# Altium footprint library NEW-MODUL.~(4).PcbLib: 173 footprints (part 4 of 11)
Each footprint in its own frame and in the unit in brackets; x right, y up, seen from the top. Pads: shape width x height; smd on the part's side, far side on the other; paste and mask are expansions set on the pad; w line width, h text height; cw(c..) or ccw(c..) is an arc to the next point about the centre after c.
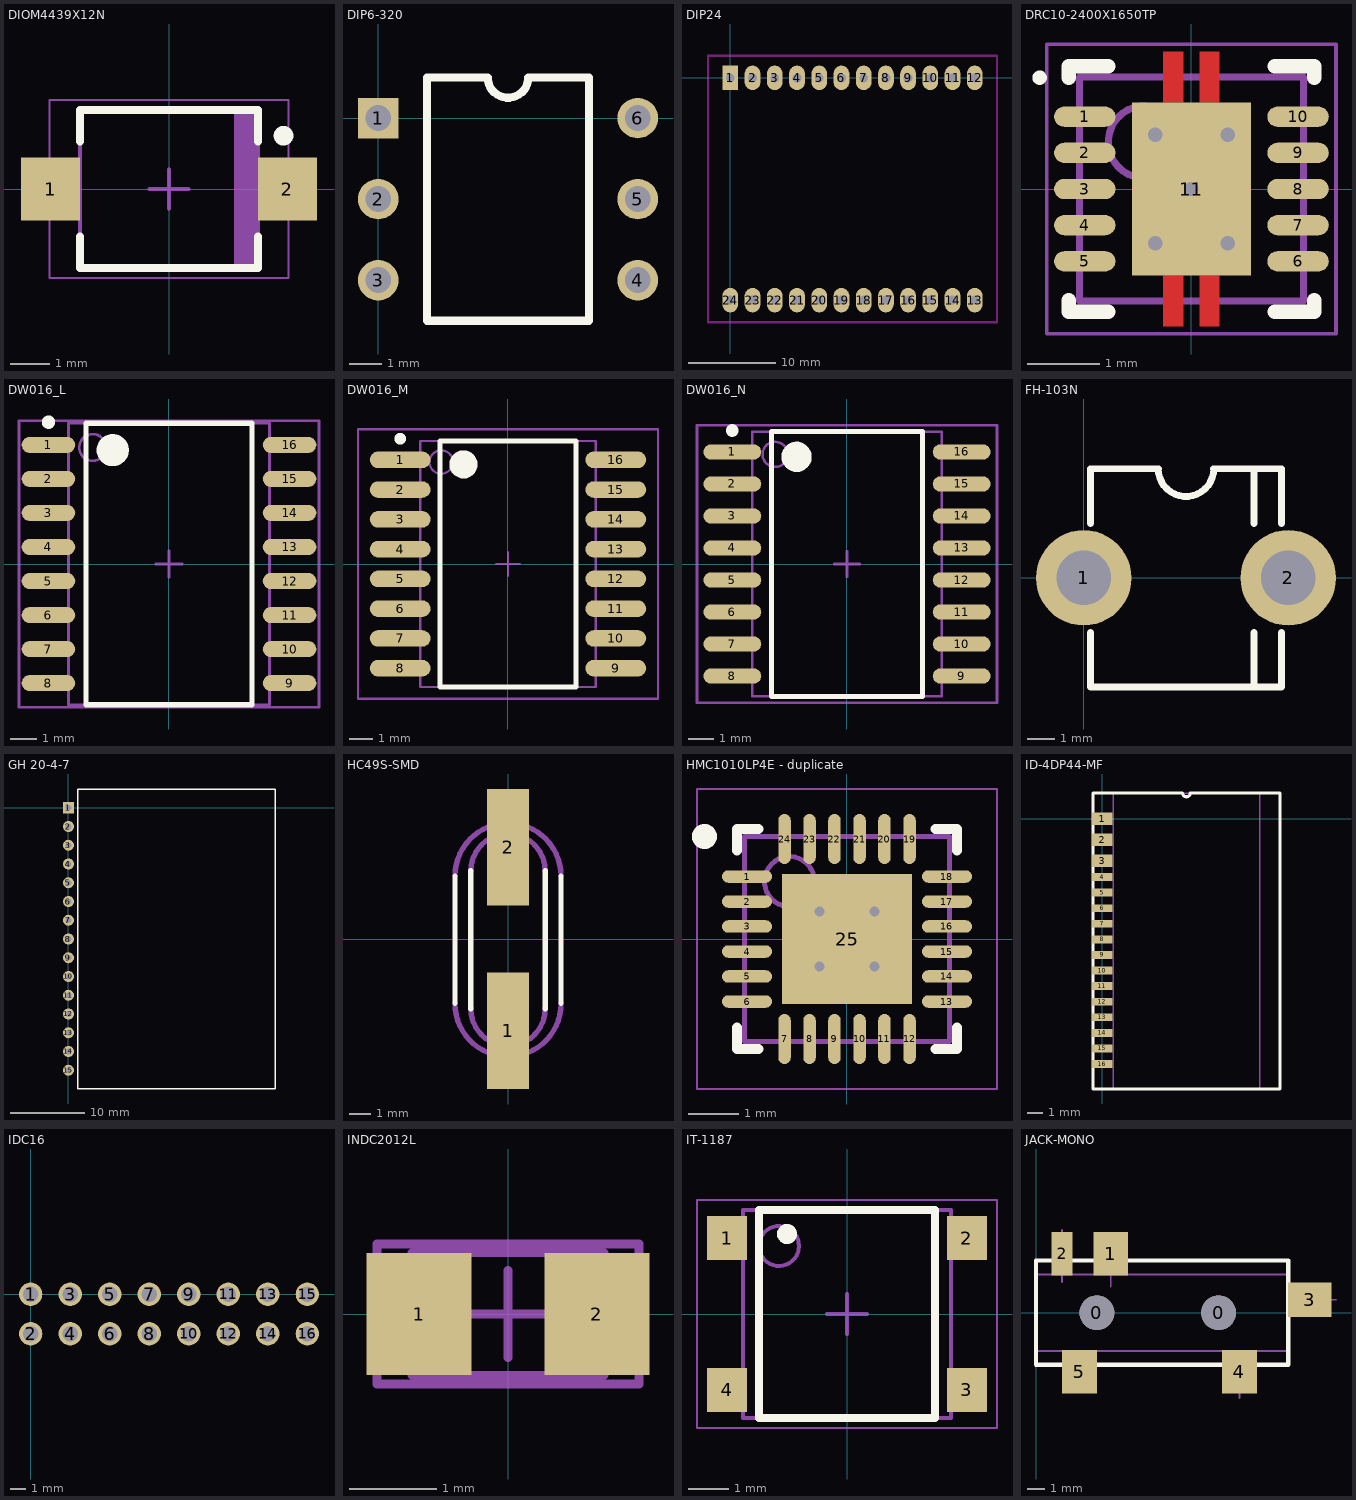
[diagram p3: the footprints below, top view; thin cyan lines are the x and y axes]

## DIOM4439X12N [mm] "Molded Diode, 2-Leads, Body 4,40x3,85mm, IPC Medium Density"
height 1.2
pads (2):
  rect 1.5x1.6 smd: 1(-3,0) 2(3,0)
Top Overlay:
  circle w0.25: c2.9,1.35 r0.125
  lines w0.2: -2.25,-1.2 -2.25,-2 2.25,-2 2.25,-1.2 ; -2.25,1.2 -2.25,2 2.25,2 2.25,1.2
Mechanical 13:
  rectangle: 1.645,-2 2.25,2
  lines w0.1: -2.25,-2 2.25,-2 2.25,2 -2.25,2 -2.25,-2
Mechanical 15:
  lines w0.05: -3.025,-2.25 3.025,-2.25 3.025,2.25 -3.025,2.25 -3.025,-2.25
  lines w0.1: -0.5,0 0.5,0 ; 0,-0.5 0,0.5
3D body: height 1.2, standoff 0, extent -2.25,-2 2.25,2

## DIP6-320 [mil]
pads (6):
  rect 50x50 hole 32: 1(0,0)
  round 50 hole 32: 2(0,-100) 3(0,-200) 4(320,-200) 5(320,-100) 6(320,0)
Top Overlay:
  lines w10: 60,-250 260,-250 260,50 185,50 cw(c160,50) 135,50 60,50 60,-250
3D body "4N33_DIL06.stp": height 177.17, standoff -115.06, extent -13.76,-267.71 328.71,70.87

## DIP24 [mm]
pads (24):
  rect 1.8x2.8 hole 1: 1(0,0)
  oval 1.8x2.8 hole 1: 2(2.54,0) 3(5.08,0) 4(7.62,0) 5(10.16,0) 6(12.7,0) 7(15.24,0) 8(17.78,0) 9(20.32,0) 10(22.86,0) 11(25.4,0) 12(27.94,0) 13(27.94,-25.4) 14(25.4,-25.4) 15(22.86,-25.4) 16(20.32,-25.4) 17(17.78,-25.4) 18(15.24,-25.4) 19(12.7,-25.4) 20(10.16,-25.4) 21(7.62,-25.4) 22(5.08,-25.4) 23(2.54,-25.4) 24(0,-25.4)
Bottom Overlay:
  lines w0.254: -2.54,-13.97 ccw(c-2.54,-12.7) -2.54,-11.43
Keep-Out Layer:
  lines w0.254: -2.54,-27.94 30.48,-27.94 30.48,2.54 -2.54,2.54 -2.54,-27.94
3D body "User Library-PLS-1.step": height 8.44, standoff -3, extent 26.67,-26.67 29.21,-24.13
3D body "User Library-PLS-1.step": height 8.44, standoff -3, extent 24.13,-26.67 26.67,-24.13
3D body "User Library-PLS-1.step": height 8.44, standoff -3, extent 21.59,-26.67 24.13,-24.13
3D body "User Library-PLS-1.step": height 8.44, standoff -3, extent 19.05,-26.67 21.59,-24.13
3D body "User Library-PLS-1.step": height 8.44, standoff -3, extent 16.51,-26.67 19.05,-24.13
3D body "User Library-PLS-1.step": height 8.44, standoff -3, extent 13.97,-26.67 16.51,-24.13
3D body "User Library-PLS-1.step": height 8.44, standoff -3, extent 11.43,-26.67 13.97,-24.13
3D body "User Library-PLS-1.step": height 8.44, standoff -3, extent 8.89,-26.67 11.43,-24.13
3D body "User Library-PLS-1.step": height 8.44, standoff -3, extent 6.35,-26.67 8.89,-24.13
3D body "User Library-PLS-1.step": height 8.44, standoff -3, extent 3.81,-26.67 6.35,-24.13
3D body "User Library-PLS-1.step": height 8.44, standoff -3, extent 1.27,-26.67 3.81,-24.13
3D body "User Library-PLS-1.step": height 8.44, standoff -3, extent -1.27,-26.67 1.27,-24.13
3D body "User Library-PLS-1.step": height 8.44, standoff -3, extent 26.67,-1.27 29.21,1.27
3D body "User Library-PLS-1.step": height 8.44, standoff -3, extent 24.13,-1.27 26.67,1.27
3D body "User Library-PLS-1.step": height 8.44, standoff -3, extent 21.59,-1.27 24.13,1.27
3D body "User Library-PLS-1.step": height 8.44, standoff -3, extent 19.05,-1.27 21.59,1.27
3D body "User Library-PLS-1.step": height 8.44, standoff -3, extent 16.51,-1.27 19.05,1.27
3D body "User Library-PLS-1.step": height 8.44, standoff -3, extent 13.97,-1.27 16.51,1.27
3D body "User Library-PLS-1.step": height 8.44, standoff -3, extent 11.43,-1.27 13.97,1.27
3D body "User Library-PLS-1.step": height 8.44, standoff -3, extent 8.89,-1.27 11.43,1.27
3D body "User Library-PLS-1.step": height 8.44, standoff -3, extent 6.35,-1.27 8.89,1.27
3D body "User Library-PLS-1.step": height 8.44, standoff -3, extent 3.81,-1.27 6.35,1.27
3D body "User Library-PLS-1.step": height 8.44, standoff -3, extent 1.27,-1.27 3.81,1.27
3D body "User Library-PLS-1.step": height 8.44, standoff -3, extent -1.27,-1.27 1.27,1.27

## DRC10-2400X1650TP [mm] "SON, 10-Leads, Body 3x3mm, Pitch 0.5mm, Thermal Pad 2.4x1.65mm, TI Recommended"
height 1
pads (11):
  oval 0.85x0.28 smd paste-0.025 mask+0.07: 1(-1.475,1) 2(-1.475,0.5) 3(-1.475,0) 4(-1.475,-0.5) 5(-1.475,-1) 6(1.475,-1) 7(1.475,-0.5) 8(1.475,0) 9(1.475,0.5) 10(1.475,1)
  rect 1.65x2.4 smd paste-0.825 mask+0.07: 11(0,0)
via 0.5,-0.75 diameter 0.5 hole 0.2
via -0.5,-0.75 diameter 0.5 hole 0.2
via -0.5,0.75 diameter 0.5 hole 0.2
via 0.5,0.75 diameter 0.5 hole 0.2
via 0,0 diameter 0.5 hole 0.2
Top Layer:
  rectangle: -0.39,-1.9 -0.11,-1.2
  region: 0.39,-1.2 0.11,-1.2 0.11,-1.9 0.39,-1.9
  region: 0.39,1.9 0.11,1.9 0.11,1.2 0.39,1.2
  rectangle: -0.39,1.2 -0.11,1.9
Top Overlay:
  circle w0.1: c-2.1,1.54 r0.05
  lines w0.2: -1.7,-1.54 -1.7,-1.7 -1.15,-1.7 ; -1.7,1.54 -1.7,1.7 -1.15,1.7 ; 1.15,-1.7 1.7,-1.7 1.7,-1.54 ; 1.15,1.7 1.7,1.7 1.7,1.54
Top Paste:
  rectangle: -0.79,-1.16 -0.11,-0.11
  region: 0.79,-0.11 0.11,-0.11 0.11,-1.16 0.79,-1.16
  region: 0.79,1.16 0.11,1.16 0.11,0.11 0.79,0.11
  rectangle: -0.38,-1.88 -0.12,-1.38
  region: 0.38,-1.38 0.12,-1.38 0.12,-1.88 0.38,-1.88
  region: 0.38,1.88 0.12,1.88 0.12,1.38 0.38,1.38
  rectangle: -0.38,1.38 -0.12,1.88
  rectangle: -0.79,0.11 -0.11,1.16
Mechanical 13:
  circle w0.1: c-0.65,0.65 r0.5
  lines w0.1: -1.55,-1.55 1.55,-1.55 1.55,1.55 -1.55,1.55 -1.55,-1.55
Mechanical 15:
  lines w0.05: -2,-2 2,-2 2,2 -2,2 -2,-2
3D body: height 1, standoff 0, extent -1.55,-1.55 1.55,1.55

## DW016_L [mm] "16-Pin Plastic Small Outline Integrated Circuit 1.27 mm Pitch, IPC High Density"
height 2.65
pads (16):
  oval 2x0.6 smd: 1(-4.5,4.445) 2(-4.5,3.175) 3(-4.5,1.905) 4(-4.5,0.635) 5(-4.5,-0.635) 6(-4.5,-1.905) 7(-4.5,-3.175) 8(-4.5,-4.445) 9(4.5,-4.445) 10(4.5,-3.175) 11(4.5,-1.905) 12(4.5,-0.635) 13(4.5,0.635) 14(4.5,1.905) 15(4.5,3.175) 16(4.5,4.445)
Top Overlay:
  circle w0.25: c-4.5,5.295 r0.125
  circle w0.6: c-2.1,4.25 r0.3
  lines w0.2: -3.1,-5.25 -3.1,5.25 3.1,5.25 3.1,-5.25 -3.1,-5.25
Mechanical 13:
  circle w0.1: c-2.85,4.35 r0.5
  lines w0.1: -3.75,-5.25 -3.75,5.25 3.75,5.25 3.75,-5.25 -3.75,-5.25
Mechanical 15:
  lines w0.1: -0.5,0 0.5,0 ; 0,-0.5 0,0.5 ; -5.6,-5.35 -5.6,5.35 5.6,5.35 5.6,-5.35 -5.6,-5.35
3D body: height 2.65, standoff 0, extent -3.75,-5.25 3.75,5.25

## DW016_M [mm] "16-Pin Plastic Small Outline Integrated Circuit 1.27 mm Pitch, IPC Low Density"
height 2.65
pads (16):
  oval 2.6x0.7 smd: 1(-4.6,4.445) 2(-4.6,3.175) 3(-4.6,1.905) 4(-4.6,0.635) 5(-4.6,-0.635) 6(-4.6,-1.905) 7(-4.6,-3.175) 8(-4.6,-4.445) 9(4.6,-4.445) 10(4.6,-3.175) 11(4.6,-1.905) 12(4.6,-0.635) 13(4.6,0.635) 14(4.6,1.905) 15(4.6,3.175) 16(4.6,4.445)
Top Overlay:
  circle w0.6: c-1.9,4.25 r0.3
  circle w0.25: c-4.6,5.345 r0.125
  lines w0.2: -2.9,-5.25 2.9,-5.25 2.9,5.25 -2.9,5.25 -2.9,-5.25
Mechanical 13:
  circle w0.1: c-2.85,4.35 r0.5
  lines w0.1: -3.75,-5.25 3.75,-5.25 3.75,5.25 -3.75,5.25 -3.75,-5.25
Mechanical 15:
  lines w0.1: -0.5,0 0.5,0 ; 0,-0.5 0,0.5 ; -6.4,-5.75 6.4,-5.75 6.4,5.75 -6.4,5.75 -6.4,-5.75
3D body: height 2.65, standoff 0, extent -3.75,-5.25 3.75,5.25

## DW016_N [mm] "16-Pin Plastic Small Outline Integrated Circuit 1.27 mm Pitch, IPC Medium Density"
height 2.65
pads (16):
  oval 2.3x0.6 smd: 1(-4.55,4.445) 2(-4.55,3.175) 3(-4.55,1.905) 4(-4.55,0.635) 5(-4.55,-0.635) 6(-4.55,-1.905) 7(-4.55,-3.175) 8(-4.55,-4.445) 9(4.55,-4.445) 10(4.55,-3.175) 11(4.55,-1.905) 12(4.55,-0.635) 13(4.55,0.635) 14(4.55,1.905) 15(4.55,3.175) 16(4.55,4.445)
Top Overlay:
  circle w0.25: c-4.55,5.295 r0.125
  circle w0.6: c-2,4.25 r0.3
  lines w0.2: -3,-5.25 -3,5.25 3,5.25 3,-5.25 -3,-5.25
Mechanical 13:
  circle w0.1: c-2.85,4.35 r0.5
  lines w0.1: -3.75,-5.25 -3.75,5.25 3.75,5.25 3.75,-5.25 -3.75,-5.25
Mechanical 15:
  lines w0.1: -0.5,0 0.5,0 ; 0,-0.5 0,0.5 ; -5.95,-5.5 -5.95,5.5 5.95,5.5 5.95,-5.5 -5.95,-5.5
3D body "User Library-SOIC16-300.step": height 2.65, standoff 0, extent -5.15,-5.15 5.15,5.15

## FH-103N [mm]
pads (2):
  round 3.5 hole 2: 1(0,0) 2(7.5,0)
Top Overlay:
  lines w0.254: 0.25,-2 0.25,-4 7.25,-4 7.25,-2 ; 0.25,2 0.25,4 2.734,4 ccw(c3.75,4) 4.766,4 7.25,4 7.25,2 ; 6.25,-4 6.25,-2 6.25,-4 ; 6.25,2 6.25,4 6.25,2
3D body "User Library-LF-102071.step": height 10.89, standoff -3.6, extent -0.24,-3.95 7.86,3.95

## GH 20-4-7 [mm]
height 3
pads (15):
  rect 1.5x1.5 hole 0.8: 1(0,0)
  round 1.5 hole 0.8: 2(0,-2.54) 3(0,-5.08) 4(0,-7.62) 5(0,-10.16) 6(0,-12.7) 7(0,-15.24) 8(0,-17.78) 9(0,-20.32) 10(0,-22.86) 11(0,-25.4) 12(0,-27.94) 13(0,-30.48) 14(0,-33.02) 15(0,-35.56)
Top Overlay:
  lines w0.2: 1.25,-38.1 28,-38.1 28,2.54 1.25,2.54 1.25,-38.1

## HC49S-SMD [mm]
pads (2):
  rect 2x5.5 smd: 1(0,-4.318) 2(0,4.318)
Top Overlay:
  lines w0.25: -2.5,-3.04 -2.5,2.96 ; -1.75,-3.29 -1.75,3.21 ; 1.75,-3.29 1.75,3.21 ; 2.5,-3.04 2.5,2.96
Mechanical 1:
  lines w0.25: -2.5,-3.036 ccw(c0,-3.04) 2.5,-3.036 ; -2.5,2.964 cw(c0,2.96) 2.5,2.964 ; -1.75,-3.287 ccw(c0,-3.29) 1.75,-3.287 ; -1.75,3.213 cw(c0,3.21) 1.75,3.213
3D body "User Library-SMU-4.step": height 4, standoff 0, extent -2.4,-6.25 2.4,6.25

## HMC1010LP4E - duplicate [mm]
pads (25):
  oval 1x0.25 smd: 1(-2,1.25) 2(-2,0.75) 3(-2,0.25) 4(-2,-0.25) 5(-2,-0.75) 6(-2,-1.25) 13(2,-1.25) 14(2,-0.75) 15(2,-0.25) 16(2,0.25) 17(2,0.75) 18(2,1.25)
  oval 0.25x1 smd: 7(-1.25,-2) 8(-0.75,-2) 9(-0.25,-2) 10(0.25,-2) 11(0.75,-2) 12(1.25,-2) 19(1.25,2) 20(0.75,2) 21(0.25,2) 22(-0.25,2) 23(-0.75,2) 24(-1.25,2)
  rect 2.6x2.6 smd: 25(0,0)
via -0.55,0.55 diameter 0.5 hole 0.2
via 0.55,0.55 diameter 0.5 hole 0.2
via -0.55,-0.55 diameter 0.5 hole 0.2
via 0.55,-0.55 diameter 0.5 hole 0.2
Top Overlay:
  circle w0.25: c-2.85,2.05 r0.125
  lines w0.2: -2.2,-1.775 -2.2,-2.2 -1.775,-2.2 ; -2.2,1.775 -2.2,2.2 -1.775,2.2 ; 1.775,-2.2 2.2,-2.2 2.2,-1.775 ; 1.775,2.2 2.2,2.2 2.2,1.775
Mechanical 13:
  circle w0.1: c-1.15,1.15 r0.5
  lines w0.1: -2.05,-2.05 -2.05,2.05 2.05,2.05 2.05,-2.05 -2.05,-2.05
Mechanical 15:
  lines w0.05: -3,-3 -3,3 3,3 3,-3 -3,-3
  lines w0.1: -0.5,0 0.5,0 ; 0,-0.5 0,0.5
3D body: height 1, standoff 0, extent -2.05,-2.05 2.05,2.05

## ID-4DP44-MF [mm]
pads (16):
  rect 1.3x0.8 smd: 1(0,0) 2(0,-1.35) 3(0,-2.7)
  rect 1.3x0.5 smd: 4(0,-3.75) 5(0,-4.75) 6(0,-5.75) 7(0,-6.75) 8(0,-7.75) 9(0,-8.75) 10(0,-9.75) 11(0,-10.75) 12(0,-11.75) 13(0,-12.75) 14(0,-13.75) 15(0,-14.75) 16(0,-15.75)
Top Overlay:
  lines w0.2: -0.6,-17.35 -0.6,1.65 4.8,1.65 5.15,1.65 ccw(c5.4,1.65) 5.65,1.65 11.4,1.65 11.4,-17.35 -0.6,-17.35
Mechanical 1:
  lines w0.1: 0.7,-17.35 10.1,-17.35 10.1,1.625 0.7,1.625 0.7,-17.35

## IDC16 [mm]
pads (16):
  round 1.5 hole 1: 1(0,0) 2(0,-2.54) 3(2.54,0) 4(2.54,-2.54) 5(5.08,0) 6(5.08,-2.54) 7(7.62,0) 8(7.62,-2.54) 9(10.16,0) 10(10.16,-2.54) 11(12.7,0) 12(12.7,-2.54) 13(15.24,0) 14(15.24,-2.54) 15(17.78,0) 16(17.78,-2.54)
3D body "User Library-IDC Socket Male 16pin Straight THT Goldplated 2_54mm.STEP": height 8.9, standoff -3.5, extent -5.07,-5.52 22.85,3.33

## INDC2012L [mm] "Chip Inductor, Body 2.0x1.2mm, IPC High Density"
height 1.1
pads (2):
  rect 1.2x1.4 smd: 1(-1.016,0) 2(1.016,0)
Mechanical 13:
  lines w0.1: -1.1,-0.7 1.1,-0.7 1.1,0.7 -1.1,0.7 -1.1,-0.7
Mechanical 15:
  lines w0.1: -0.5,0 0.5,0 ; 0,-0.5 0,0.5 ; -1.5,-0.8 1.5,-0.8 1.5,0.8 -1.5,0.8 -1.5,-0.8
3D body "User Library-ind_0805.step": height 0.95, standoff 0, extent -1,-0.6 1,0.6

## IT-1187 [mm] "SOIC, 4-Leads, Body 5,20x5,20mm, Pitch 1,27mm, IPC Medium Density"
height 1.5
pads (4):
  rect 1x1.1 smd: 1(-3,1.9) 2(3,1.9) 3(3,-1.9) 4(-3,-1.9)
Top Overlay:
  circle w0.25: c-1.5,2 r0.125
  lines w0.2: -2.2,-2.6 -2.2,2.6 2.2,2.6 2.2,-2.6 -2.2,-2.6
Mechanical 13:
  circle w0.1: c-1.7,1.7 r0.5
  lines w0.1: -2.6,-2.6 -2.6,2.6 2.6,2.6 2.6,-2.6 -2.6,-2.6
Mechanical 15:
  lines w0.05: -3.75,-2.85 -3.75,2.85 3.75,2.85 3.75,-2.85 -3.75,-2.85
  lines w0.1: -0.5,0 0.5,0 ; 0,-0.5 0,0.5
3D body "User Library-IT-1187.step": height 1.5, standoff 0, extent -3.2,-2.6 3.2,2.6

## JACK-MONO [mm]
pads (7):
  round 2 hole 2 unplated: 0(3.5,0) 0(10.5,0)
  rect 2x2.5 smd: 1(4.3,3.4) 4(11.7,-3.4) 5(2.5,-3.4)
  rect 1.2x2.5 smd: 2(1.5,3.4)
  rect 2.5x2 smd: 3(15.75,0.75)
Top Overlay:
  lines w0.254: 0,-3 14.5,-3 14.5,3 0,3 0,0 0,-3
Mechanical 1:
  lines w0.1: 0,-2.2 14.5,-2.2 ; 0,2.2 14.5,2.2 ; 1.5,1.75 1.5,4.75 ; 2.5,-4.5 2.5,-2.2 ; 4.3,1.5 4.3,4.5 ; 11.7,-4.9 11.7,-2.2 ; 14.5,0.75 17.25,0.75
3D body "User Library-35RASMT4BHNTRX.step": height 5.26, standoff -0.74, extent -2.5,-4.5 16.5,4.5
